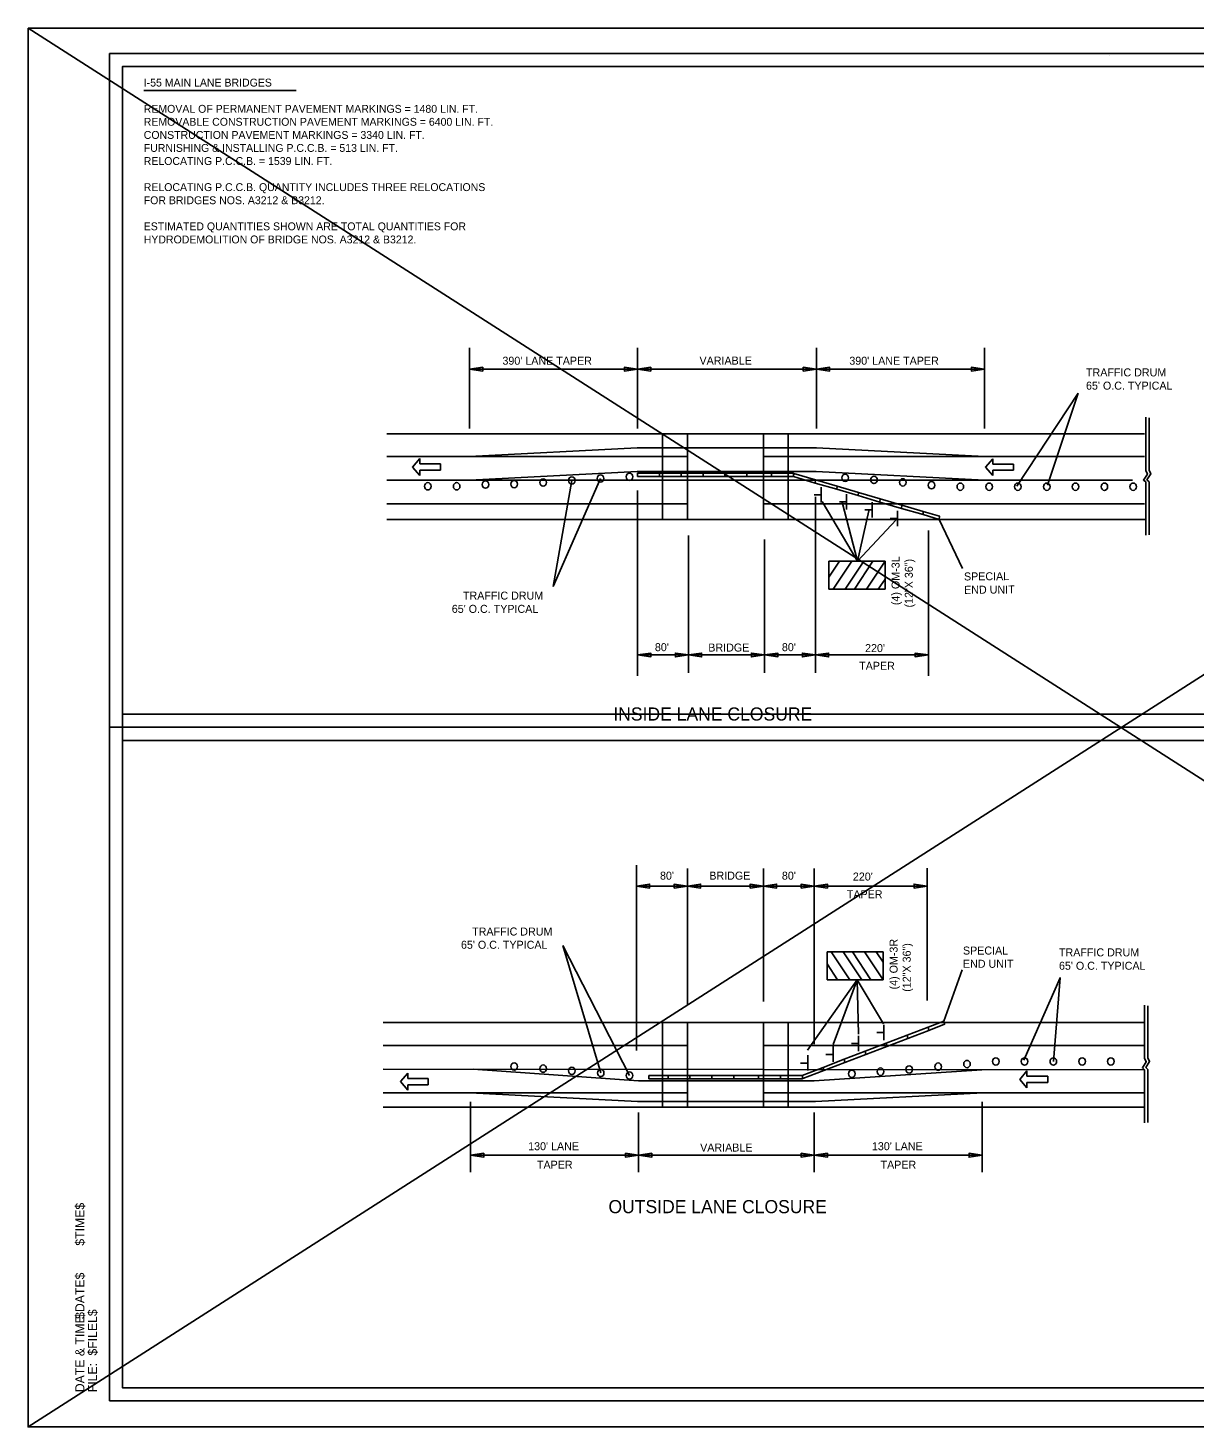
# Model space of a CAD drawing. Extents: x 13528 to 25043, y 7635 to 10612.
# Drawn here: x 21767 to 22655, y 9545 to 10612 of the extents above; entities that cross this region are included whole.
import ezdxf

# ---------------------------------------------------------------- set-up
doc = ezdxf.new("R2010")
doc.units = 0
for name, color, linetype in [('Default', 7, 'Continuous'), ('R_Border', 7, 'Continuous'), ('R_Border Notes', 7, 'Continuous'), ('R_Border Plan-Plan', 7, 'Continuous'), ('R_Draft', 7, 'Continuous'), ('R_Revision Date Text', 7, 'Continuous'), ('STAMP_PE_CRAFTON', 7, 'Continuous'), ('STAMP_PE_FOSTER', 7, 'Continuous'), ('STAMP_PE_TXT', 7, 'Continuous'), ('STAMP_PRELIMINARY', 7, 'Continuous')]:
    doc.layers.add(name, color=color, linetype=linetype)

msp = doc.modelspace()

# ---------------------------------------------------------------- linework, layer by layer
at = {"layer": 'Default'}
for p, q in [((21766.6, 10611.5), (23433.3, 9544.9)), ((23433.3, 10611.5), (21766.6, 9544.9)), ((22103.2, 10367.6), (22103.2, 10306.2)), ((22231.2, 10367.6), (22231.2, 10306.2)), ((22231.2, 10364.4), (22231.2, 10306.2)), ((22367.5, 10367.6), (22367.5, 10306.2)), ((22367.5, 10364.4), (22367.5, 10306.2)), ((22495.6, 10367.6), (22495.6, 10306.2)), ((22103.2, 10351.4), (22231.2, 10351.4)), ((22367.5, 10351.4), (22231.2, 10351.4)), ((22495.6, 10351.4), (22367.5, 10351.4)), ((22567.1, 10333.1), (22520.3, 10262.2)), ((22543.7, 10263), (22567.1, 10333.1)), ((22618.5, 10314.7), (22618.5, 10274.2)), ((22621.1, 10314.3), (22621.1, 10274.5)), ((22346, 10302.2), (22040.1, 10302.2)), ((22250.3, 10236.9), (22250.3, 10302.2)), ((22346, 10302.2), (22250.3, 10302.2)), ((22269.2, 10236.9), (22269.2, 10302.2)), ((22327.1, 10302.2), (22327.1, 10236.9)), ((22346, 10302.2), (22346, 10236.9)), ((22617.6, 10302.2), (22346, 10302.2)), ((22269.2, 10284.7), (22040.1, 10284.7)), ((22065.3, 10283.2), (22059.7, 10276.8)), ((22065.3, 10283.2), (22065.3, 10279.2)), ((22617.6, 10284.7), (22327.1, 10284.7)), ((22501.9, 10283.1), (22496.4, 10276.7)), ((22501.9, 10283.1), (22501.9, 10279.1)), ((22059.7, 10276.8), (22065.3, 10270.4)), ((22065.3, 10279.2), (22081.1, 10279.2)), ((22065.3, 10274.4), (22081.1, 10274.4)), ((22065.3, 10274.4), (22065.3, 10270.4)), ((22081.1, 10279.2), (22081.1, 10274.4)), ((22496.4, 10276.7), (22501.9, 10270.3)), ((22501.9, 10279.1), (22517.7, 10279.1)), ((22501.9, 10274.3), (22517.7, 10274.3)), ((22501.9, 10274.3), (22501.9, 10270.3)), ((22517.7, 10279.1), (22517.7, 10274.3)), ((22608.4, 10266.7), (22040.1, 10266.7)), ((22166.8, 10185.8), (22202.9, 10268.1)), ((22181.1, 10266.6), (22166.8, 10185.8)), ((22371.1, 10261.5), (22371.1, 10249.8)), ((22618.5, 10265.4), (22618.5, 10224.9)), ((22618.5, 10265.4), (22618.5, 10224.9)), ((22621.1, 10265.6), (22621.1, 10225.2)), ((22621.1, 10265.6), (22621.1, 10225.2)), ((22231.2, 10117.7), (22231.2, 10258.8)), ((22371, 10255.7), (22365.7, 10255.7)), ((22366.8, 10120), (22366.8, 10254.1)), ((22390.5, 10256.1), (22390.5, 10244.3)), ((22269.2, 10248.7), (22040.1, 10248.7)), ((22617.6, 10248.7), (22327.1, 10248.7)), ((22390.4, 10250.2), (22385.1, 10250.2)), ((22409.7, 10244.2), (22404.4, 10244.2)), ((22409.9, 10250), (22409.9, 10238.3)), ((22429.2, 10243.4), (22429.2, 10231.7)), ((22346.8, 10236.9), (22040.1, 10236.9)), ((22346, 10236.9), (22250.3, 10236.9)), ((22618.5, 10236.9), (22346.8, 10236.9)), ((22429.1, 10237.6), (22423.8, 10237.6)), ((22478.9, 10199.5), (22461.1, 10236.9)), ((22270, 10120), (22270, 10224.5)), ((22328, 10120), (22328, 10221.5)), ((22452.9, 10117.6), (22452.9, 10228.5)), ((22270, 10133.5), (22231.2, 10133.5)), ((22328, 10133.5), (22270, 10133.5)), ((22328, 10133.5), (22366.8, 10133.5)), ((22366.8, 10133.5), (22452.9, 10133.5)), ((22230.3, 9973.2), (22230.3, 9832)), ((22269.2, 9970.8), (22269.2, 9866.4)), ((22327.1, 9970.8), (22327.1, 9869.3)), ((22365.9, 9970.8), (22365.9, 9836.7)), ((22452, 9971), (22452, 9870.1)), ((22269.2, 9957.3), (22230.3, 9957.3)), ((22327.1, 9957.3), (22269.2, 9957.3)), ((22327.1, 9957.3), (22356.4, 9957.3)), ((22356.4, 9957.3), (22452, 9957.3)), ((22203.1, 9814.8), (22174.2, 9912.1)), ((22174.2, 9912.1), (22225, 9812.9)), ((22478.5, 9893.4), (22464.7, 9854.3)), ((22617.6, 9866.5), (22617.6, 9826)), ((22620.2, 9866.1), (22620.2, 9826.3)), ((22250.3, 9853.3), (22037.2, 9853.3)), ((22250.3, 9788.7), (22250.3, 9853.3)), ((22346, 9853.3), (22250.3, 9853.3)), ((22269.2, 9788.7), (22269.2, 9853.3)), ((22327.1, 9853.3), (22327.1, 9788.7)), ((22346, 9853.3), (22346, 9788.7)), ((22617.6, 9853.3), (22346, 9853.3)), ((22418.9, 9845.6), (22413.6, 9845.6)), ((22419, 9839.8), (22419, 9851.5)), ((22269.2, 9835.7), (22037.2, 9835.7)), ((22617.6, 9835.7), (22327.1, 9835.7)), ((22380.3, 9823.2), (22380.3, 9834.9)), ((22399.5, 9837.3), (22394.2, 9837.3)), ((22399.6, 9831.5), (22399.6, 9843.2)), ((22360.9, 9816.6), (22360.9, 9828.3)), ((22380.2, 9829), (22374.8, 9829)), ((22617.6, 9817.2), (22037.2, 9817.7)), ((22050.4, 9808.2), (22056, 9814.6)), ((22056, 9810.6), (22056, 9814.6)), ((22360.8, 9822.4), (22355.4, 9822.4)), ((22522.5, 9809.9), (22528, 9816.4)), ((22528, 9812.4), (22528, 9816.4)), ((22617.6, 9817.2), (22617.6, 9776.8)), ((22617.6, 9817.2), (22617.6, 9776.8)), ((22620.2, 9817.5), (22620.2, 9777)), ((22620.2, 9817.5), (22620.2, 9777)), ((22056, 9801.8), (22050.4, 9808.2)), ((22056, 9810.6), (22071.7, 9810.6)), ((22056, 9805.8), (22071.7, 9805.8)), ((22056, 9801.8), (22056, 9805.8)), ((22071.7, 9805.8), (22071.7, 9810.6)), ((22528, 9803.5), (22522.5, 9809.9)), ((22528, 9812.4), (22543.8, 9812.4)), ((22528, 9807.5), (22543.8, 9807.5)), ((22528, 9803.5), (22528, 9807.5)), ((22543.8, 9807.5), (22543.8, 9812.4)), ((22269.2, 9799.7), (22037.2, 9799.7)), ((22103.7, 9799.7), (22231.2, 9793)), ((22103.9, 9739.1), (22103.9, 9792.9)), ((22231.2, 9793), (22366.7, 9793)), ((22617.6, 9799.7), (22327.1, 9799.7)), ((22366.7, 9793), (22494.5, 9799.7)), ((22493.9, 9739.1), (22493.9, 9792.9)), ((22346, 9788.7), (22037.2, 9788.7)), ((22232, 9739.1), (22232, 9784.7)), ((22346, 9788.7), (22250.3, 9788.7)), ((22617.6, 9788.7), (22346, 9788.7)), ((22365.9, 9739.1), (22365.9, 9784.7)), ((22103.9, 9752.1), (22232, 9752.1)), ((22232, 9752.1), (22139.5, 9752.1)), ((22167.8, 9752.1), (22232, 9752.1)), ((22365.9, 9752.1), (22232, 9752.1)), ((22458.4, 9752.1), (22365.9, 9752.1)), ((22365.9, 9752.1), (22493.9, 9752.1))]:
    msp.add_line(p, q, dxfattribs=at)
for points in [[(22103.2, 10351.4), (22113.2, 10352.9), (22113.2, 10349.9)], [(22231.2, 10351.4), (22221.2, 10352.9), (22221.2, 10349.9)], [(22231.2, 10351.4), (22241.2, 10352.9), (22241.2, 10349.9)], [(22367.5, 10351.4), (22357.5, 10352.9), (22357.5, 10349.9)], [(22367.5, 10351.4), (22377.5, 10352.9), (22377.5, 10349.9)], [(22495.6, 10351.4), (22485.6, 10352.9), (22485.6, 10349.9)], [(22231.2, 10133.5), (22241.2, 10135), (22241.2, 10132)], [(22270, 10133.5), (22260, 10135), (22260, 10132)], [(22270, 10133.5), (22280, 10135), (22280, 10132)], [(22328, 10133.5), (22318, 10135), (22318, 10132)], [(22328, 10133.5), (22338, 10135), (22338, 10132)], [(22366.8, 10133.5), (22356.8, 10135), (22356.8, 10132)], [(22366.8, 10133.5), (22376.8, 10135), (22376.8, 10132)], [(22452.9, 10133.5), (22442.9, 10135), (22442.9, 10132)], [(22230.3, 9957.3), (22240.3, 9958.8), (22240.3, 9955.8)], [(22269.2, 9957.3), (22259.2, 9958.8), (22259.2, 9955.8)], [(22269.2, 9957.3), (22279.2, 9958.8), (22279.2, 9955.8)], [(22327.1, 9957.3), (22317.1, 9958.8), (22317.1, 9955.8)], [(22327.1, 9957.3), (22337.1, 9958.8), (22337.1, 9955.8)], [(22365.9, 9957.3), (22355.9, 9958.8), (22355.9, 9955.8)], [(22365.9, 9957.3), (22375.9, 9958.8), (22375.9, 9955.8)], [(22452, 9957.3), (22442, 9958.8), (22442, 9955.8)], [(22103.9, 9752.1), (22113.9, 9753.6), (22113.9, 9750.6)], [(22232, 9752.1), (22222, 9753.6), (22222, 9750.6)], [(22232, 9752.1), (22242, 9753.6), (22242, 9750.6)], [(22365.9, 9752.1), (22355.9, 9753.6), (22355.9, 9750.6)], [(22365.9, 9752.1), (22375.9, 9753.6), (22375.9, 9750.6)], [(22493.9, 9752.1), (22483.9, 9753.6), (22483.9, 9750.6)]]:
    msp.add_lwpolyline(points, close=True, dxfattribs=at)
for points in [[(22103.2, 10284.7), (22230.8, 10291.4), (22367.5, 10291.4), (22495.6, 10284.7)], [(22103.4, 10266.7), (22230.9, 10273.4), (22367.2, 10273.4), (22495.6, 10266.7)], [(22618.5, 10265.4), (22616.8, 10266.8), (22619.8, 10271.4), (22618.5, 10274.2)], [(22618.5, 10265.4), (22616.8, 10266.8), (22619.8, 10271.4), (22618.5, 10274.2)], [(22621.1, 10265.6), (22619.4, 10267.1), (22622.4, 10271.7), (22621.1, 10274.5)], [(22621.1, 10265.6), (22619.4, 10267.1), (22622.4, 10271.7), (22621.1, 10274.5)], [(22371.8, 10250.5), (22398.9, 10205), (22428.2, 10236.6)], [(22387.1, 10249.9), (22398.9, 10205), (22407.4, 10243.4)], [(22360.8, 9832.3), (22398.6, 9885.9), (22418.6, 9852.2)], [(22380.4, 9836.5), (22398.6, 9885.9), (22399.6, 9844.3)], [(22525.6, 9824.6), (22553.3, 9887.4), (22548.1, 9823.6)], [(22617.6, 9817.2), (22616, 9818.7), (22618.9, 9823.2), (22617.6, 9826)], [(22617.6, 9817.2), (22616, 9818.7), (22618.9, 9823.2), (22617.6, 9826)], [(22620.2, 9817.5), (22618.6, 9819), (22621.5, 9823.5), (22620.2, 9826.3)], [(22620.2, 9817.5), (22618.6, 9819), (22621.5, 9823.5), (22620.2, 9826.3)], [(22105.8, 9817.7), (22232, 9808.9), (22365.8, 9808.9), (22493.7, 9817.3)]]:
    msp.add_lwpolyline(points, dxfattribs=at)
at = {"layer": 'R_Border'}
for centre in [(22225, 10269.4), (22071.4, 10262.1), (22093.3, 10262.1), (22115.3, 10263.4), (22137.2, 10263.8), (22159.2, 10265), (22181.1, 10266.6), (22203, 10268.1), (22389.4, 10268.6), (22411.4, 10267), (22433.3, 10265.1), (22455.3, 10262.9), (22477.2, 10261.8), (22499.2, 10261.8), (22521.1, 10261.8), (22543.1, 10261.8), (22565, 10261.8), (22587, 10261.8), (22608.9, 10261.8), (22482.3, 9821.6), (22504.2, 9823.6), (22526.2, 9823.6), (22548.1, 9823.6), (22570, 9823.6), (22592, 9823.6), (22137.2, 9819.7), (22159.2, 9818.1), (22181.1, 9816.4), (22203.1, 9814.8), (22225, 9812.9), (22394.5, 9814.2), (22416.4, 9815.8), (22438.2, 9817.5), (22460.3, 9819.6)]:
    msp.add_ellipse(centre, major_axis=(0, 2.81), ratio=0.888889, dxfattribs=at)
at = {"layer": 'R_Border Notes'}
msp.add_line((21854.8, 10564), (21971, 10564), dxfattribs=at)
at = {"layer": 'R_Border Plan-Plan'}
msp.add_line((21828.6, 10078.4), (23409.5, 10078.4), dxfattribs=at)
at = {"layer": 'R_Draft'}
for p, q in [((21828.6, 10592.1), (23409.5, 10592.1)), ((21828.6, 9564.8), (21828.6, 10592.1)), ((22591.2, 10590.8), (22591.2, 10590.8)), ((22591.2, 10590.8), (22591.2, 10590.8)), ((21828.6, 9564.8), (21828.6, 9564.8)), ((23409.5, 9564.8), (21828.6, 9564.8))]:
    msp.add_line(p, q, dxfattribs=at)
at = {"layer": 'R_Revision Date Text'}
for points in [[(21766.6, 10611.5), (23433.3, 10611.5), (23433.3, 9544.9), (21766.6, 9544.9)], [(23399.5, 10088.4), (21838.6, 10088.4), (21838.6, 10582.1), (23086.3, 10582.1), (23086.3, 10532.7), (23174, 10532.7), (23294.5, 10532.7), (23294.5, 10421), (23399.5, 10421)], [(21838.6, 10582.1), (23086.3, 10582.1), (23086.3, 10532.7), (23174, 10532.7), (23294.5, 10532.7), (23294.5, 10421), (23399.5, 10421), (23399.5, 9574.8), (21838.6, 9574.8)], [(21838.6, 10068.4), (23399.5, 10068.4), (23399.5, 9574.8), (21838.6, 9574.8)]]:
    msp.add_lwpolyline(points, close=True, dxfattribs=at)
at = {"layer": 'STAMP_PE_FOSTER'}
for p, q in [((22377.1, 10183.6), (22377.1, 10205)), ((22377.1, 10183.6), (22419.8, 10183.6)), ((22375.6, 9907.2), (22418.3, 9907.2)), ((22375.6, 9907.2), (22375.6, 9885.9))]:
    msp.add_line(p, q, dxfattribs=at)
msp.add_lwpolyline([(22377.1, 10205), (22419.8, 10205), (22419.8, 10183.6)], dxfattribs=at)
at = {"layer": 'STAMP_PE_TXT'}
for points in [[(22231.2, 10269.5), (22247.8, 10269.5), (22247.8, 10272), (22231.2, 10272)], [(22247.8, 10269.5), (22264.5, 10269.5), (22264.5, 10272), (22247.8, 10272)], [(22264.5, 10269.5), (22281.1, 10269.5), (22281.1, 10272), (22264.5, 10272)], [(22281.1, 10269.5), (22297.8, 10269.5), (22297.8, 10272), (22281.1, 10272)], [(22297.8, 10269.5), (22314.5, 10269.5), (22314.5, 10272), (22297.8, 10272)], [(22314.5, 10269.5), (22333.4, 10269.5), (22333.4, 10272), (22314.5, 10272)], [(22333.4, 10269.5), (22350.1, 10269.5), (22350.1, 10272), (22333.4, 10272)], [(22350.1, 10269.5), (22366.5, 10264.6), (22366.8, 10267.1), (22350.4, 10271.9)], [(22366.5, 10264.6), (22383, 10259.8), (22383.3, 10262.3), (22366.8, 10267.1)], [(22383, 10259.8), (22399.4, 10255), (22399.7, 10257.4), (22383.3, 10262.3)], [(22399.4, 10255), (22415.9, 10250.1), (22416.1, 10252.6), (22399.7, 10257.4)], [(22415.9, 10250.1), (22432.3, 10245.3), (22432.6, 10247.8), (22416.1, 10252.6)], [(22432.3, 10245.3), (22448.8, 10240.5), (22449, 10242.9), (22432.6, 10247.8)], [(22448.8, 10240.5), (22461.1, 10236.9), (22461.4, 10239.3), (22449, 10242.9)], [(22436.7, 9843.6), (22452.7, 9849.7), (22453.2, 9847.3), (22437.2, 9841.2)], [(22452.7, 9849.7), (22464.7, 9854.3), (22465.2, 9851.9), (22453.2, 9847.3)], [(22404.7, 9831.3), (22420.7, 9837.5), (22421.2, 9835), (22405.2, 9828.9)], [(22420.7, 9837.5), (22436.7, 9843.6), (22437.2, 9841.2), (22421.2, 9835)], [(22372.7, 9819), (22388.7, 9825.2), (22389.1, 9822.8), (22373.1, 9816.6)], [(22388.7, 9825.2), (22404.7, 9831.3), (22405.2, 9828.9), (22389.1, 9822.8)], [(22356.7, 9812.9), (22372.7, 9819), (22373.1, 9816.6), (22357.1, 9810.5)], [(22239.9, 9812.9), (22254.5, 9812.9), (22254.5, 9810.4), (22239.9, 9810.4)], [(22254.5, 9812.9), (22271.1, 9812.9), (22271.1, 9810.4), (22254.5, 9810.4)], [(22271.1, 9812.9), (22287.8, 9812.9), (22287.8, 9810.4), (22271.1, 9810.4)], [(22287.8, 9812.9), (22304.5, 9812.9), (22304.5, 9810.4), (22287.8, 9810.4)], [(22304.5, 9812.9), (22323.4, 9812.9), (22323.4, 9810.4), (22304.5, 9810.4)], [(22323.4, 9812.9), (22340.1, 9812.9), (22340.1, 9810.4), (22323.4, 9810.4)], [(22340.1, 9812.9), (22356.8, 9812.9), (22356.8, 9810.4), (22340.1, 9810.4)]]:
    msp.add_lwpolyline(points, close=True, dxfattribs=at)
at = {"layer": 'STAMP_PRELIMINARY'}
for p, q in [((22385.2, 10205), (22377.1, 10192.8)), ((22377.1, 10205), (22419.8, 10205)), ((22377.1, 10205), (22377.1, 10192.8)), ((22377.1, 10192.8), (22385.2, 10205)), ((22385.2, 10205), (22377.1, 10205)), ((22380.2, 10183.7), (22394.4, 10205)), ((22419.8, 10205), (22385.2, 10205)), ((22403.6, 10205), (22389.4, 10183.7)), ((22394.4, 10205), (22403.6, 10205)), ((22396.5, 10183.7), (22410.6, 10205)), ((22419.8, 10205), (22405.6, 10183.6)), ((22410.6, 10205), (22419.8, 10205)), ((22419.8, 10183.6), (22419.8, 10205)), ((22419.8, 10205), (22419.8, 10191.4)), ((22419.8, 10191.4), (22414.6, 10183.6)), ((22419.8, 10191.4), (22414.6, 10183.6)), ((22419.8, 10183.6), (22419.8, 10191.4)), ((22414.6, 10183.6), (22419.8, 10183.6)), ((22378.7, 9907.1), (22392.9, 9885.9)), ((22402.1, 9885.9), (22387.9, 9907.1)), ((22394.9, 9907.1), (22409.1, 9885.9)), ((22418.3, 9885.9), (22404.1, 9907.2)), ((22418.3, 9899.4), (22413.1, 9907.2)), ((22418.3, 9899.4), (22413.1, 9907.2)), ((22413.1, 9907.2), (22418.3, 9907.2)), ((22418.3, 9907.2), (22418.3, 9885.9)), ((22418.3, 9907.2), (22418.3, 9899.4)), ((22418.3, 9885.9), (22418.3, 9899.4)), ((22383.7, 9885.9), (22375.6, 9898)), ((22375.6, 9885.9), (22375.6, 9898)), ((22375.6, 9898), (22383.7, 9885.9)), ((22375.6, 9885.9), (22418.3, 9885.9)), ((22383.7, 9885.9), (22375.6, 9885.9)), ((22418.3, 9885.9), (22383.7, 9885.9)), ((22392.9, 9885.9), (22402.1, 9885.9)), ((22409.1, 9885.9), (22418.3, 9885.9))]:
    msp.add_line(p, q, dxfattribs=at)

# ---------------------------------------------------------------- texts
at = {"layer": 'Default'}
for s, height, p in [("390' LANE TAPER", 6.1, (22128.2, 10354.8)), ('VARIABLE', 6.1, (22278.4, 10354.9)), ("390' LANE TAPER", 6.1, (22392.6, 10354.8)), ('TRAFFIC DRUM', 6.1, (22573, 10345.9)), ("65' O.C. TYPICAL", 6.1, (22573, 10335.8)), ('TRAFFIC DRUM', 6.1, (22098.1, 10175.7)), ("65' O.C. TYPICAL", 6.1, (22089.6, 10165.6)), ("80'", 6.1, (22244.4, 10136.4)), ('BRIDGE', 6.1, (22285.1, 10136.1)), ("80'", 6.1, (22341.2, 10136.4)), ("220'", 6.1, (22404.6, 10135.7)), ('TAPER', 6.1, (22400.1, 10122.2)), ('INSIDE LANE CLOSURE ', 10.002, (22212.7, 10083.5)), ("80'", 6.1, (22248.3, 9962.2)), ('BRIDGE', 6.1, (22285.9, 9962.2)), ("80'", 6.1, (22341.2, 9962.2)), ('TRAFFIC DRUM', 6.1, (22105.1, 9919.6)), ("65' O.C. TYPICAL", 6.1, (22096.6, 9909.5)), ('SPECIAL', 6.1, (22479.2, 9905.1)), ('TRAFFIC DRUM', 6.1, (22552.4, 9903.7)), ('END UNIT', 6.1, (22479.2, 9895)), ("65' O.C. TYPICAL", 6.1, (22552.4, 9893.5)), ("130' LANE", 6.1, (22147.8, 9755.9)), ('VARIABLE', 6.1, (22278.9, 9754.9)), ("130' LANE", 6.1, (22409.8, 9755.9)), ('TAPER', 6.1, (22154.5, 9741.8)), ('OUTSIDE LANE CLOSURE', 10.002, (22209, 9707.9))]:
    msp.add_text(s, height=height, dxfattribs=at).set_placement(p)
for s, rotation, p in [('SPECIAL', 0.434, (22480, 10190.3)), ('END UNIT', 0.434, (22480.1, 10180.1)), ("220'", 360, (22395.3, 9961.5)), ('TAPER', 360, (22390.7, 9948)), ('TAPER', 360, (22416.4, 9741.8))]:
    msp.add_text(s, height=6.1, rotation=rotation, dxfattribs=at).set_placement(p)
at = {"layer": 'R_Border Notes'}
for s, p in [('I-55 MAIN LANE BRIDGES', (21854.8, 10566.9)), ('REMOVAL OF PERMANENT PAVEMENT MARKINGS = 1480 LIN. FT.', (21854.8, 10546.9)), ('REMOVABLE CONSTRUCTION PAVEMENT MARKINGS = 6400 LIN. FT.', (21854.8, 10537)), ('CONSTRUCTION PAVEMENT MARKINGS = 3340 LIN. FT.', (21854.8, 10527)), ('FURNISHING & INSTALLING P.C.C.B. = 513 LIN. FT.', (21854.8, 10517.1)), ('RELOCATING P.C.C.B. = 1539 LIN. FT.', (21854.8, 10507.1)), ('RELOCATING P.C.C.B. QUANTITY INCLUDES THREE RELOCATIONS ', (21854.8, 10487.2)), ('FOR BRIDGES NOS. A3212 & B3212.', (21854.8, 10477.2)), ('ESTIMATED QUANTITIES SHOWN ARE TOTAL QUANTITIES FOR ', (21854.8, 10457.3)), ('HYDRODEMOLITION OF BRIDGE NOS. A3212 & B3212. ', (21854.8, 10447.3))]:
    msp.add_text(s, height=6, dxfattribs=at).set_placement(p)
for s, height, p in [('$TIME$', 6.98, (21809.6, 9683.1)), ('$DATE$', 6.98, (21809.6, 9627.3)), ('$FILEL$', 6.98, (21819.2, 9599.3)), ('DATE & TIME:', 6.984, (21809.6, 9571.4)), ('FILE: ', 6.98, (21819.2, 9571.4))]:
    msp.add_text(s, height=height, rotation=90, dxfattribs=at).set_placement(p)
at = {"layer": 'STAMP_PE_CRAFTON'}
for s, p in [('(4) OM-3L', (22430.9, 10171.5)), ('(12"X 36")', (22441, 10169.7)), ('(4) OM-3R', (22429.4, 9878.5)), ('(12"X 36")', (22439.4, 9876.7))]:
    msp.add_text(s, height=6.1, rotation=90, dxfattribs=at).set_placement(p)

doc.saveas('drawing.dxf')
